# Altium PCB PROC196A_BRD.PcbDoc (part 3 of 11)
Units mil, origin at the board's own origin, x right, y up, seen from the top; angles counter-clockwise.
Board outline 3346.45 x 4921.26 mil, 8 copper layers (Top Layer, GND1, SIG1, PWR1, PWR2, SIG2, GND2, Bottom Layer), stack 54.534 mil thick; 736 components, 498 nets, 3030 pads, 1279 vias.
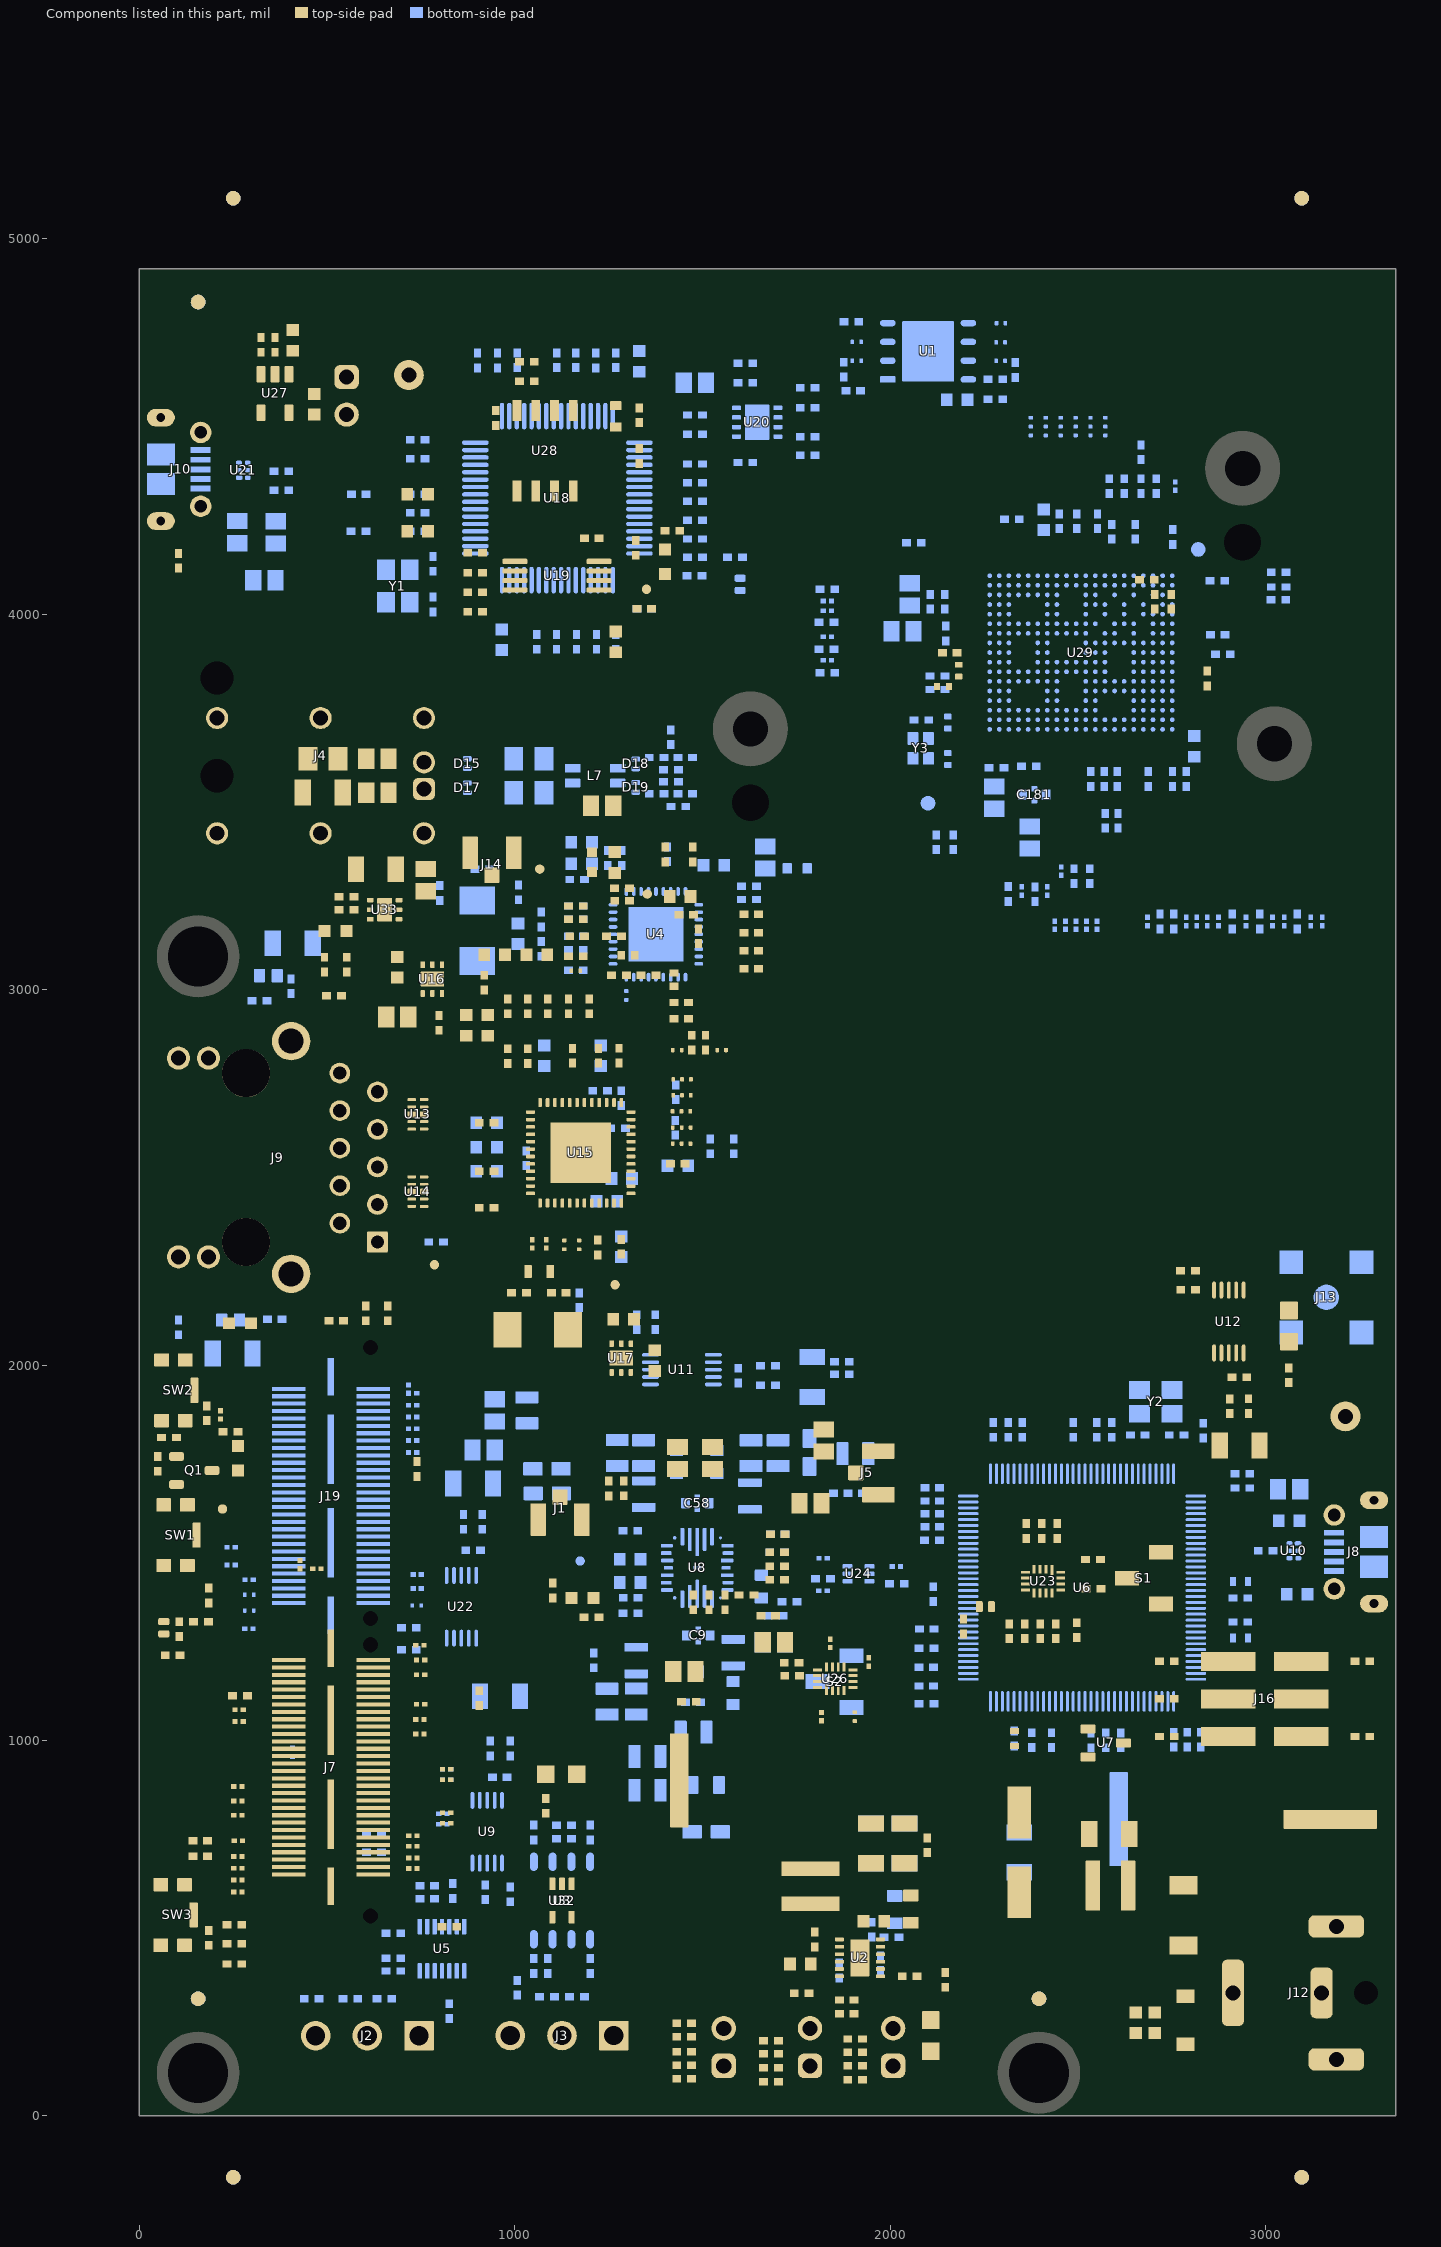
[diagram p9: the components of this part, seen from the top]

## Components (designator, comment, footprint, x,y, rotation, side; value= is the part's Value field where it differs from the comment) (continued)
U1 "GD25B64CWAG" FP-GD25B64CWAG_WSON8-IPC_C 2101.26,4700.85 r0 bottom
U2 "LM63635DQDRRRQ1" DRR0012E-MFG 1919.6,420.63 r0 top
U3 "TCAN1042HGVDQ1" D0008A_L 1125.93,573.58 r270 bottom
U4 "DP83TG720SWRNDRQ1" RND0036A 1376.2,3147.56 r0 bottom locked
U5 "TCAN1043ADYYRQ1" DYY0014A-MFG 806.31,444.86 r270 bottom
U6 "TM4C1294NCPDTT3" PDT0128A 2511.49,1407.16 r90 bottom locked
U7 "LM4040C25QDBZR" DBZ0003A_N 2574.48,993.51 r0 top
U8 "LP877451A1RXVRQ1" RXV0028A-MFG 1486.13,1459.75 r180 bottom locked
U9 "INA226AIDGSR" DGS0010A_L 926.74,756.92 r90 bottom
U10 "TPD4E004DRYR" DRY0006A 3075.82,1505.18 r180 bottom
U11 "INA226AIDGSR" DGS0010A_L 1445.36,1987.85 r0 bottom
U12 "INA226AIDGSR" DGS0010A_L 2902.35,2116.06 r270 top
U13 "TPD4E05U06DQAR" DQA0010A 742.07,2668.11 r0 top
U14 "TPD4E05U06DQAR" DQA0010A 742.07,2462.03 r0 top
U15 "DP83867ERGZR" RGZ0048B 1175.93,2565.54 r0 top
U16 "TPS73501DRVR" DRV0006A 780.58,3028.35 r90 top
U17 "TLV73310PQDRVRQ1" DRV0006A 1283.94,2018.66 r270 top
U18 "FT4232HL" LQFP64_N 1113.67,4309.69 r0 bottom
U19 "93LC46B-I/ST" TSSOP-8 1112.63,4102.86 r0 top
U20 "TPS79601DRBR" DRB0008B 1645.89,4511.81 r0 bottom
U21 "TPD4E004DRYR" DRY0006A 276.82,4383.75 r0 bottom
U22 "INA226AIDGSR" DGS0010A_L 857.87,1356.04 r90 bottom
U23 "TS3A5018RSVR" RSV0016A 2407.55,1424.47 r270 top
U24 "TMP112AIDRLR" DRL0006A 1915.92,1443.85 r180 bottom
U26 "TS3A5018RSVR" RSV0016A 1854.01,1164.54 r90 top
U27 "TPS78417QDBVRQ1" DBV0005A-MFG 361.36,4588.4 r270 top
U28 "CAV24C02WE-GT3" SOIC-8 1080.83,4435.85 r90 top
U29 "AWR2E44P" AMX0278A-MFG 2508.41,3898.25 r0 bottom
U32 "SN74LVC1G04QDCKRQ1" DCK0005A_N 1125.93,573.58 r270 top
U33 "TPS7B8133QDRVRQ1" DRV0006A 653.41,3213.22 r0 top
Y1 "NX3225SA-12.000M-STD-CRS-2" NDK_NX3225SA 688.79,4075.43 r0 bottom
Y2 "NX3225SA-16.000M-STD-CRS-2" NDK_NX3225SA 2707.65,1902.17 r270 bottom
Y3 "NX2016SA-50M-STD-CZS-3" FP-NX2016SA-50M-STD-CZS-3_SMT4_2MM0_1MM6-MFG 2081.21,3642.74 r270 bottom
Y4 "ABM3-25.000MHZ-D2Y-T" XTAL_ABM3 1061.17,2093.9 r0 top
Y5 "ABM3-25.000MHZ-D2W-T" XTAL_ABM3 899.95,3156.78 r90 bottom
ZZ1 "This Assembly Note is for PCB labels only" AssemblyNoteLabel 187.12,5373.65 r0 top
ZZ2 "These assemblies are ESD sensitive, ESD precautions shall be observed." AssemblyNote 187.12,5264.77 r0 top
ZZ3 "These assemblies must be clean and free from flux and all contaminants. Use of no clean flux is not acceptable." AssemblyNote 179,5572 r0 top
ZZ4 "These assemblies must comply with workmanship standards IPC-A-610 Class 2, unless otherwise specified." AssemblyNote 177,5497 r0 top

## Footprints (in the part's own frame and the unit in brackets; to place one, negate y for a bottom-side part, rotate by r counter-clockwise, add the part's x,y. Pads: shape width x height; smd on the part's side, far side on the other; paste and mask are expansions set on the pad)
142-0711-201 [mil] "Emerson Connectivity recommended land pattern"
  round 68 smd: 1(0,0)
  rect 63x63 smd: 2(-93.5,-93.5) 2(-93.5,93.5) 2(93.5,-93.5) 2(93.5,93.5)
  Top Layer region: -47.5,64.83 -57.02,57.02 -67.05,44.8 -74.5,30.86 -79.09,15.73 -80.64,0 -79.09,-15.73 -74.5,-30.86 -67.05,-44.8 -57.02,-57.02 -47.5,-64.83 -47.5,-140 -140.5,-140 -140.5,140 -47.5,140
  Top Layer region: 140.5,-140 47.5,-140 47.5,-64.83 57.02,-57.02 67.05,-44.8 74.5,-30.86 79.09,-15.73 80.64,0 79.09,15.73 74.5,30.86 67.05,44.8 57.02,57.02 47.5,64.83 47.5,140 140.5,140
  body extent -125,-125 125,125, height 349
0201_033L [mm] "0201"
  rect 0.36x0.32 smd mask+0.048: 1(-0.28,0) 2(0.28,0)
  body extent -0.31,-0.16 0.31,0.16, height 0.33
0201L [mm] "Data from Kemet datasheet CC101_COM dated 7/28/11"
  rect 0.36x0.32 smd mask+0.048: 1(-0.28,0) 2(0.28,0)
  body extent -0.31,-0.16 0.31,0.16, height 0.26
0402_065L [mm] "0402"
  rect 0.6x0.5 smd: 1(-0.5,0) 2(0.5,0)
  body extent -0.55,-0.3 0.55,0.3, height 0.65
0402_070 [mil] "SMD, 2-Leads, Body 1.2x0.7mm, Height 0.7mm"
  rect 15x24 smd: 1(-20,0) 2(20,0)
  body extent -24,-14 24,14, height 28
0402L [mm] "0402 from SM-752 data"
  rect 0.6x0.5 smd: 1(-0.5,0) 2(0.5,0)
  body extent -0.55,-0.3 0.55,0.3, height 0.6
0603L [mm] "0603 from SM-752 data"
  rect 0.8x0.85 smd: 1(-0.7,0) 2(0.7,0)
  silkscreen extent -0.07,-0.33 0.07,0.33, body extent -0.87,-0.47 0.87,0.47, height 1
0805_155 [mm] "SMD, 2-Leads, Body 2x1.25mm"
  rrect12% 0.825x1.55 smd: 1(-0.875,0) 2(0.875,0)
  silkscreen extent -0.15,-0.77 0.15,0.77, body extent -1.15,-0.77 1.15,0.77, height 1.55
0805_HV [mil] "0805 with 30mil clearance between pads"
  rect 50x63 smd: 1(-40,0) 2(40,0)
  silkscreen extent -74,-40 74,40, body extent -43,-29 43,29, height 57
0805L [mm] "0805 from SM-752 data"
  rect 1.1x1.4 smd: 1(-0.75,0) 2(0.75,0)
  body extent -1.1,-0.72 1.1,0.72, height 1.45
1206_180L [mm] "1206_180"
  rect 1.1x1.75 smd: 1(-1.35,0) 2(1.35,0)
  silkscreen extent -0.4,-0.77 0.4,0.77, body extent -1.75,-0.95 1.75,0.95, height 1.8
1206L [mm] "1206 from SM-752 data"
  rect 1.1x1.75 smd: 1(-1.35,0) 2(1.35,0)
  silkscreen extent -0.4,-0.77 0.4,0.77, body extent -1.7,-0.9 1.7,0.9, height 1.35
-UKCA_Filled [mil]
  silkscreen extent -118,-118 118,118
AMX0278A-MFG [mm]
  round 0.32 smd paste+0 mask+0.07: A1(-6.175,5.2) A2(-5.525,5.2) A3(-4.875,5.2) A4(-4.225,5.2) A5(-3.575,5.2) A6(-2.925,5.2) A7(-2.275,5.2) A8(-1.625,5.2) A9(-0.975,5.2) A10(-0.325,5.2) A11(0.325,5.2) A12(0.975,5.2) A13(1.625,5.2) A14(2.275,5.2) A15(2.925,5.2) A16(3.575,5.2) A17(4.225,5.2) A18(4.875,5.2) A19(5.525,5.2) A20(6.175,5.2) B1(-6.175,4.55) B2(-5.525,4.55) B3(-4.875,4.55) B4(-4.225,4.55) B5(-3.575,4.55) B6(-2.925,4.55) B7(-2.275,4.55) B8(-1.625,4.55) B9(-0.975,4.55) B10(-0.325,4.55) B11(0.325,4.55) B12(0.975,4.55) B13(1.625,4.55) B14(2.275,4.55) B15(2.925,4.55) B16(3.575,4.55) B17(4.225,4.55) B18(4.875,4.55) B19(5.525,4.55) B20(6.175,4.55) C1(-6.175,3.9) C2(-5.525,3.9) C3(-4.875,3.9) C4(-4.225,3.9) C5(-3.575,3.9) C6(-2.925,3.9) C7(-2.275,3.9) C8(-1.625,3.9) C9(-0.975,3.9) C10(-0.325,3.9) C11(0.325,3.9) C12(0.975,3.9) C16(3.575,3.9) C17(4.225,3.9) C18(4.875,3.9) C19(5.525,3.9) C20(6.175,3.9) D1(-6.175,3.25) D2(-5.525,3.25) D3(-4.875,3.25) D7(-2.275,3.25) D8(-1.625,3.25) D11(0.325,3.25) D12(0.975,3.25) D16(3.575,3.25) D17(4.225,3.25) D18(4.875,3.25) D19(5.525,3.25) D20(6.175,3.25) E1(-6.175,2.6) E2(-5.525,2.6) E3(-4.875,2.6) E7(-2.275,2.6) E8(-1.625,2.6) E11(0.325,2.6) E12(0.975,2.6) E13(1.625,2.6) E14(2.275,2.6) E15(2.925,2.6) E16(3.575,2.6) E17(4.225,2.6) E18(4.875,2.6) E19(5.525,2.6) E20(6.175,2.6) F1(-6.175,1.95) F2(-5.525,1.95) F3(-4.875,1.95) F4(-4.225,1.95) F5(-3.575,1.95) F6(-2.925,1.95) F7(-2.275,1.95) F8(-1.625,1.95) F11(0.325,1.95) F12(0.975,1.95) F13(1.625,1.95) F14(2.275,1.95) F15(2.925,1.95) F16(3.575,1.95) F17(4.225,1.95) F18(4.875,1.95) F19(5.525,1.95) F20(6.175,1.95) G1(-6.175,1.3) G2(-5.525,1.3) G3(-4.875,1.3) G4(-4.225,1.3) G5(-3.575,1.3) G6(-2.925,1.3) G7(-2.275,1.3) G8(-1.625,1.3) G9(-0.975,1.3) G10(-0.325,1.3) G11(0.325,1.3) G12(0.975,1.3) G13(1.625,1.3) G16(3.575,1.3) G17(4.225,1.3) G18(4.875,1.3) G19(5.525,1.3) G20(6.175,1.3) H1(-6.175,0.65) H2(-5.525,0.65) H3(-4.875,0.65) H6(-2.925,0.65) H7(-2.275,0.65) H8(-1.625,0.65) H9(-0.975,0.65) H10(-0.325,0.65) H11(0.325,0.65) H12(0.975,0.65) H13(1.625,0.65) H16(3.575,0.65) H17(4.225,0.65) H18(4.875,0.65) H19(5.525,0.65) H20(6.175,0.65) J1(-6.175,0) J2(-5.525,0) J3(-4.875,0) J6(-2.925,0) J7(-2.275,0) J11(0.325,0) J12(0.975,0) J13(1.625,0) J16(3.575,0) J17(4.225,0) J18(4.875,0) J19(5.525,0) J20(6.175,0) K1(-6.175,-0.65) K2(-5.525,-0.65) K3(-4.875,-0.65) K6(-2.925,-0.65) K7(-2.275,-0.65) K11(0.325,-0.65) K12(0.975,-0.65) K13(1.625,-0.65) K14(2.275,-0.65) K15(2.925,-0.65) K16(3.575,-0.65) K17(4.225,-0.65) K18(4.875,-0.65) K19(5.525,-0.65) K20(6.175,-0.65) L1(-6.175,-1.3) L2(-5.525,-1.3) L3(-4.875,-1.3) L4(-4.225,-1.3) L5(-3.575,-1.3) L6(-2.925,-1.3) L7(-2.275,-1.3) L8(-1.625,-1.3) L9(-0.975,-1.3) L10(-0.325,-1.3) L11(0.325,-1.3) L13(1.625,-1.3) L14(2.275,-1.3) L16(3.575,-1.3) L18(4.875,-1.3) L19(5.525,-1.3) L20(6.175,-1.3) M1(-6.175,-1.95) M2(-5.525,-1.95) M3(-4.875,-1.95) M4(-4.225,-1.95) M5(-3.575,-1.95) M6(-2.925,-1.95) M7(-2.275,-1.95) M8(-1.625,-1.95) M9(-0.975,-1.95) M10(-0.325,-1.95) M11(0.325,-1.95) M12(0.975,-1.95) M14(2.275,-1.95) M15(2.925,-1.95) M16(3.575,-1.95) M18(4.875,-1.95) M19(5.525,-1.95) M20(6.175,-1.95) N1(-6.175,-2.6) N2(-5.525,-2.6) N3(-4.875,-2.6) N7(-2.275,-2.6) N8(-1.625,-2.6) N11(0.325,-2.6) N13(1.625,-2.6) N15(2.925,-2.6) N17(4.225,-2.6) N18(4.875,-2.6) N19(5.525,-2.6) N20(6.175,-2.6) P1(-6.175,-3.25) P2(-5.525,-3.25) P3(-4.875,-3.25) P7(-2.275,-3.25) P8(-1.625,-3.25) P11(0.325,-3.25) P12(0.975,-3.25) P13(1.625,-3.25) P15(2.925,-3.25) P17(4.225,-3.25) P19(5.525,-3.25) P20(6.175,-3.25) R1(-6.175,-3.9) R2(-5.525,-3.9) R3(-4.875,-3.9) R4(-4.225,-3.9) R5(-3.575,-3.9) R6(-2.925,-3.9) R7(-2.275,-3.9) R8(-1.625,-3.9) R11(0.325,-3.9) R12(0.975,-3.9) R14(2.275,-3.9) R16(3.575,-3.9) R18(4.875,-3.9) R19(5.525,-3.9) R20(6.175,-3.9) T1(-6.175,-4.55) T2(-5.525,-4.55) T3(-4.875,-4.55) T4(-4.225,-4.55) T5(-3.575,-4.55) T6(-2.925,-4.55) T7(-2.275,-4.55) T8(-1.625,-4.55) T9(-0.975,-4.55) T10(-0.325,-4.55) T11(0.325,-4.55) T12(0.975,-4.55) T13(1.625,-4.55) T14(2.275,-4.55) T15(2.925,-4.55) T16(3.575,-4.55) T17(4.225,-4.55) T18(4.875,-4.55) T19(5.525,-4.55) T20(6.175,-4.55) U1(-6.175,-5.2) U2(-5.525,-5.2) U3(-4.875,-5.2) U4(-4.225,-5.2) U5(-3.575,-5.2) U6(-2.925,-5.2) U7(-2.275,-5.2) U8(-1.625,-5.2) U9(-0.975,-5.2) U10(-0.325,-5.2) U11(0.325,-5.2) U12(0.975,-5.2) U13(1.625,-5.2) U14(2.275,-5.2) U15(2.925,-5.2) U16(3.575,-5.2) U17(4.225,-5.2) U18(4.875,-5.2) U19(5.525,-5.2) U20(6.175,-5.2)
  silkscreen extent -6.8,-6.05 6.8,6.05, body extent -6.75,-6 6.75,6, height 1.24
AssemblyNote [mil] "Assembly Note"
AssemblyNoteLabel [mil] "Assembly Note for PCB Labels"
CE_Mark_5mm [mil] "Minimum text height for CE Mark"
  silkscreen extent -138,-98 138,98
CONN_105017-0001 [mm] "Molex Micro USB-B"
  rect 0.4x1.35 smd: 1(-1.3,1.35) 2(-0.65,1.35) 3(0,1.35) 4(0.65,1.35) 5(1.3,1.35)
  oval 1.2x1.9 hole 0.6 slot 1.3 at 90 deg: 6(-3.5,-1.35) 9(3.5,-1.35)
  rect 1.5x1.9 smd: 7(-1,-1.35) 8(1,-1.35)
  round 1.45 hole 0.85: 10(2.5,1.35) 11(-2.5,1.35)
  Top Layer region: 3.5,-2.3 2.3,-2.3 2.3,-0.4 3.5,-0.4
  Top Layer region: -3.5,-0.4 -2.3,-0.4 -2.3,-2.3 -3.5,-2.3
  silkscreen extent -4.1,-0.2 4.1,1.4, body extent -4.1,-3.93 4.1,1.5, height 2.72
CUI_PJ-063AH [mm] "DC POWER JACK, R/A, TH"
  rrect50% 1.5x4.5 hole 1 square: 1(-4.5,0)
  rrect50% 1.5x3.45 hole 1 square: 2(1.5,0)
  oval 1.35x1.3 hole 1.6 unplated mask+0.102: ALIGN(4.5,0)
  rrect50% 3.75x1.5 hole 1 square: S1(2.5,-4.5) S2(2.5,4.5)
  body extent -5.5,-5.15 7.5,5.15, height 9
D0008A_L [mm] "SOIC, 8-Leads, Body 4.9x3.9mm, Pitch 1.27mm, IPC High Density"
  oval 1.25x0.55 smd: 1(-2.625,1.905) 2(-2.625,0.635) 3(-2.625,-0.635) 4(-2.625,-1.905) 5(2.625,-1.905) 6(2.625,-0.635) 7(2.625,0.635) 8(2.625,1.905)
  silkscreen extent -3.1,-2.5 0.9,2.5, body extent -3,-2.45 3,2.45, height 1.63
DBV0005A-MFG [mm]
  rrect17% 1.1x0.6 smd paste+0 mask+0: 1(-1.3,0.95) 2(-1.3,0) 3(-1.3,-0.95) 4(1.3,-0.95) 5(1.3,0.95)
  silkscreen extent -1.5,-1.53 0.87,2.01, body extent -1.95,-1.78 1.95,1.78, height 0.25
DBZ0003A_N [mm] "SOT23, 3-Leads, Body 2.9x1.3mm, Pitch 0.95mm, Lead Span 2.4mm, IPC Medium Density"
  rrect17% 1x0.6 smd: 1(-1.2,0.95) 2(-1.2,-0.95) 3(1.2,0)
  silkscreen extent 0.2,-1.5 0.7,1.5, body extent -1.26,-1.46 1.26,1.46, height 0.98
DCK0005A_N [mm] "SOT353, 5-Leads, Body 2x1.3mm, Pitch 0.65mm, Lead Span 2.1mm, IPC Medium Density"
  rrect25% 0.85x0.4 smd: 1(-1.125,0.65) 2(-1.125,0) 3(-1.125,-0.65) 4(1.125,-0.65) 5(1.125,0.65)
  silkscreen extent -1.48,-1.02 0.55,1.1, body extent -1.14,-1 1.14,1, height 0.95
DGS0010A_L [mm] "TSSOP, 10-Leads, Body 3x3mm, Pitch 0.5mm, IPC High Density"
  oval 1.15x0.25 smd: 1(-2.125,1) 2(-2.125,0.5) 3(-2.125,0) 4(-2.125,-0.5) 5(-2.125,-1) 6(2.125,-1) 7(2.125,-0.5) 8(2.125,0) 9(2.125,0.5) 10(2.125,1)
  silkscreen extent -2.65,-1.55 0.9,1.55, body extent -2.45,-1.5 2.45,1.5, height 0.96
DPY0002A [mm] "X1SON-2"
  rrect57% 0.35x0.6 smd paste-0.5 mask-0.05: 1(-0.325,0) 2(0.325,0)
  rrect33% 0.3x0.5 on Bottom Paste: 1S(-0.35,0) 2S(0.35,0)
  silkscreen extent -0.85,-0.02 -0.8,0.03, body extent -0.5,-0.3 0.5,0.3, height 0.45
DQA0010A [mm] "SON, 10-Leads, Body 1x2.5mm, Pitch 0.5mm, TI Recommended"
  rrect50% 0.565x0.2 smd: 1(-0.417,1) 2(-0.417,0.5) 4(-0.417,-0.5) 5(-0.417,-1) 6(0.417,-1) 7(0.417,-0.5) 9(0.417,0.5) 10(0.417,1)
  rrect28% 0.565x0.36 on Top Paste: 3(-0.417,0) 8(0.417,0)
  rrect25% 0.565x0.4 smd paste-0.2: 3(-0.417,0) 8(0.417,0)
  silkscreen extent -0.67,-1.45 0.55,1.45, body extent -0.55,-1.3 0.55,1.3, height 0.56
DRB0008B [mm] "SON, 8-Leads, Body 3x3mm, Pitch 0.65mm, Thermal Pad 2.4x1.65mm, TI Recommended"
  rrect33% 0.6x0.3 smd: 1(-1.4,0.975) 2(-1.4,0.325) 3(-1.4,-0.325) 4(-1.4,-0.975) 5(1.4,-0.975) 6(1.4,-0.325) 7(1.4,0.325) 8(1.4,0.975)
  rrect9% 1.47x1.06 on Bottom Paste: 9(0,-0.63) 9(0,0.63)
  rrect6% 1.65x2.4 smd paste-1.2: 9(0,0)
  silkscreen extent -1.73,-1.73 1.73,1.73, body extent -1.5,-1.5 1.5,1.5, height 0.96
DRL0006A [mm] "SOTFL, 6-Flat Leads, Body 1.2x1.6x0.6mm, Pitch 0.5mm, TI recommended"
  rrect33% 0.67x0.3 smd: 1(-0.74,0.5) 2(-0.74,0) 3(-0.74,-0.5) 4(0.74,-0.5) 5(0.74,0) 6(0.74,0.5)
  silkscreen extent -0.9,-0.95 0.5,0.95, body extent -0.8,-0.8 0.8,0.8, height 0.61
DRR0012E-MFG [mm]
  rrect40% 0.62x0.25 smd paste+0 mask+0: 1(-1.39,1.25) 2(-1.39,0.75) 3(-1.39,0.25) 4(-1.39,-0.25) 5(-1.39,-0.75) 6(-1.39,-1.25) 7(1.39,-1.25) 8(1.39,-0.75) 9(1.39,-0.25) 10(1.39,0.25) 11(1.39,0.75) 12(1.39,1.25)
  rrect8% 1.3x2.5 smd paste-1000 mask+0: 13(0,0)
  silkscreen extent -2.37,-1.75 1.55,1.75, body extent -1.8,-1.65 1.8,1.65, height 0.25
DRV0006A [mm] "SON, 6-Leads, Body 2x2mm, Pitch 0.65mm, Thermal Pad 1.6x1mm, TI Recommended"
  rrect33% 0.45x0.3 smd: 1(-0.975,0.65) 2(-0.975,0) 3(-0.975,-0.65) 4(0.975,-0.65) 5(0.975,0) 6(0.975,0.65)
  rrect14% 1x0.7 on Top Paste: 7(0,0.45) 7(0,-0.45)
  rrect10% 1x1.6 smd paste-0.5: 7(0,0)
  silkscreen extent -1.05,-1.2 1.05,1.2, body extent -1.05,-1.05 1.05,1.05, height 0.81
DRY0006A [mm] "USON-6"
  rrect67% 0.45x0.3 smd paste-0.05 mask-0.05: 1(-0.275,0.5)
  rrect67% 0.4x0.3 smd paste-0.05 mask-0.05: 2(-0.3,0) 3(-0.3,-0.5) 4(0.3,-0.5) 5(0.3,0) 6(0.3,0.5)
  body extent -0.5,-0.72 0.5,0.73, height 0.58
DYY0014A-MFG [mm]
  rrect33% 1.05x0.3 smd paste+0 mask+0: 1(-1.5,1.5) 2(-1.5,1) 3(-1.5,0.5) 4(-1.5,0) 5(-1.5,-0.5) 6(-1.5,-1) 7(-1.5,-1.5) 8(1.5,-1.5) 9(1.5,-1) 10(1.5,-0.5) 11(1.5,0) 12(1.5,0.5) 13(1.5,1) 14(1.5,1.5)
  silkscreen extent -2.72,-2.15 1.05,2.15, body extent -1.63,-2.1 1.63,2.1, height 1.1
ESD_Overlay_Small [mil]
  silkscreen extent -62,-48 64,61
FCC_disclaimer [mil]
Fiducial10-20 [mm]
  round 1 smd paste-1 mask+0.5: 1(0,0)
  Top Layer keep-out circle w1.178: c0,0 r0.5
"FP-1909763-1_SMT_JACK _CONN-MFG" [mm]
  rrect10% 1x1.05 smd paste+0 mask+0: 1(0,-1.6)
  rrect10% 1.05x2.2 smd paste+0 mask+0: 2(-1.475,-0.075) 3(1.475,-0.075)
  silkscreen extent -1.43,-2.8 1.43,1.5, body extent -2.1,-2.22 2.1,1.6, height 0.25
FP-ACT1210L-201-2P-TL00_SMD4-MFG [mm]
  rrect17% 1.05x0.6 smd paste+0 mask+0: 1(-1.525,0.5) 2(-1.525,-0.5) 3(1.525,-0.5) 4(1.525,0.5)
  silkscreen extent -1.83,-1.35 1.7,1.87, body extent -1.95,-1.25 1.95,1.25, height 2.5
FP-BLM18AG102SH1D_0603-MFG [mm]
  rrect15% 0.65x0.7 smd paste+0 mask+0: 1(-0.675,0) 2(0.675,0)
  silkscreen extent -0.87,-0.72 0.87,0.72, body extent -0.8,-0.4 0.8,0.4, height 0.95
"FP-BLM18KG601SH1_0603 (1608 Metric)-MFG" [mm]
  rrect15% 0.65x0.7 smd paste+0 mask+0: 1(-0.675,0) 2(0.675,0)
  silkscreen extent -0.87,-0.75 0.87,0.75, body extent -1.1,-0.58 1.1,0.58, height 0.25
FP-C0603C104K4RACAUTO_0603-MFG [mm]
  rrect13% 0.75x0.9 smd paste+0 mask+0: 1(-0.6,0) 2(0.6,0)
  silkscreen extent -0.87,-0.85 0.88,0.85, body extent -0.8,-0.4 0.8,0.4, height 0.87
FP-CGA4J1X7R1H475K125AC_0805-MFG [mm]
  rrect13% 0.8x1.05 smd paste+0 mask+0: 1(-0.925,0) 2(0.925,0)
  silkscreen extent -0.15,-0.72 0.15,0.72, body extent -1.43,-0.82 1.43,0.82, height 0.25
FP-CRCW06031M00FKEAC_0603-MFG [mm]
  rrect20% 0.5x0.9 smd paste+0 mask+0: 1(-0.75,0) 2(0.75,0)
  silkscreen extent -0.82,-0.85 0.82,0.85, body extent -1.1,-0.55 1.1,0.55, height 0.25
FP-ERJ-1GNF33R2C_0201-MFG [mm]
  rrect40% 0.25x0.3 smd paste+0 mask+0: 1(-0.3,0) 2(0.3,0)
  silkscreen extent -0.32,-0.54 0.32,0.54, body extent -0.3,-0.15 0.3,0.15, height 0.26
FP-GCJ188C70J475KE02J_0603-MFG [mm]
  rrect13% 0.75x0.9 smd paste+0 mask+0: 1(-0.775,0) 2(0.775,0)
  silkscreen extent -0.9,-0.87 0.9,0.87, body extent -0.8,-0.4 0.8,0.4, height 1
FP-GCM1555C1H3R9BA16D_0402-MFG [mm]
  rrect25% 0.4x0.5 smd paste+0 mask+0: 1(-0.4,0) 2(0.4,0)
  silkscreen extent -0.53,-0.65 0.53,0.65, body extent -0.5,-0.25 0.5,0.25, height 0.55
FP-GD25B64CWAG_WSON8-IPC_C [mm]
  rrect23% 1.059x0.436 smd paste+0 mask+0: 1(-2.727,1.905)
  rrect100% 1.059x0.436 smd paste+0 mask+0: 2(-2.727,0.635) 3(-2.727,-0.635) 4(-2.727,-1.905) 5(2.727,-1.905) 6(2.727,-0.635) 7(2.727,0.635) 8(2.727,1.905)
  rrect3% 3.5x4.1 smd paste-1000 mask+0: 9(0,0)
  silkscreen extent -3.92,-2.5 3,2.5, body extent -3,-2.5 3,2.5, height 0.8
FP-GRT155R70J105KE01D_0402-MFG [mm]
  rrect25% 0.4x0.5 smd paste+0 mask+0: 1(-0.4,0) 2(0.4,0)
  silkscreen extent -0.53,-0.63 0.53,0.63, body extent -0.5,-0.25 0.5,0.25, height 0.55
FP-HCJ0603ZT0R00_0603-MFG [mm]
  rrect11% 1.3x0.92 smd paste+0 mask+0: 1(-0.95,0) 2(0.95,0)
  silkscreen extent -0.9,-0.83 0.9,0.83, body extent -0.8,-0.4 0.8,0.4, height 0.7
FP-LPJG16414A4NL_CONN_RJ45-MFG [mm]
  rrect7% 1.4x1.4 hole 0.9 paste-2539.97 mask+0: 1(-5.715,9.015)
  round 1.4 hole 0.9 paste-2539.97 mask+0: 2(-4.445,6.475) 3(-3.175,9.015) 4(-1.905,6.475) 5(-0.635,9.015) 6(0.635,6.475) 7(1.905,9.015) 8(3.175,6.475) 9(4.445,9.015) 10(5.715,6.475)
  round 1.57 hole 1.02 paste-2539.97 mask+0: 11(6.725,-2.415) 12(6.725,-4.445) 13(-6.725,-2.415) 14(-6.725,-4.445)
  round 2.6 hole 1.7 paste-2539.97 mask+0: 15(-7.875,3.175) 16(7.875,3.175)
  round 3.25 hole 3.25 unplated paste-2539.97 mask+0: ""(-5.715,0.125) ""(5.715,0.125)
  silkscreen extent -9.72,-10.75 8.1,10.75, body extent -9.94,-10.88 9.87,10.63, height 15.47
FP-MPZ2012S101ATD25_0805-MFG [mm]
  rrect13% 0.8x1.2 smd paste+0 mask+0: 1(-0.9,0) 2(0.9,0)
  silkscreen extent -0.13,-0.72 0.13,0.72, body extent -1,-0.63 1,0.63, height 1.05
FP-NFM18HC105C1C3D_0603-MFG [mm]
  rrect17% 0.6x0.7 smd paste+0 mask+0: 1(-0.8,0) 3(0.8,0)
  rrect25% 0.4x0.4 smd paste+0 mask+0: 2(0,-0.4) 2(0,0.4)
  silkscreen extent -1.66,-0.97 0.85,0.97, body extent -0.8,-0.4 0.8,0.4, height 0.7
FP-NX2016SA-50M-STD-CZS-3_SMT4_2MM0_1MM6-MFG [mm]
  rrect13% 0.85x0.75 smd paste+0 mask+0: 1(-0.675,-0.525) 2(0.675,-0.525) 3(0.675,0.525) 4(-0.675,0.525)
  silkscreen extent -1.48,-1.58 1.48,0.85, body extent -1,-0.8 1,0.8, height 0.5
FP-OSTTF030161_PTH_TERMINAL_BLOCK-MFG [mm]
  rrect5% 2x2 hole 1.3 paste-2539.97 mask+0: 1(-3.5,-0.45)
  round 2 hole 1.3 paste-2539.97 mask+0: 2(0,-0.45) 3(3.5,-0.45)
  silkscreen extent -6.63,-4.3 5.9,4.3, body extent -6,-4.4 6,4.4, height 0.25
"FP-TFM201610ALMAR24MTAA_0806 (2016 Metric)-MFG" [mm]
  rrect17% 0.6x1.6 smd paste+0 mask+0: 1(-0.9,0) 2(0.9,0)
  silkscreen extent -0.23,-0.9 0.23,0.9, body extent -1,-0.8 1,0.8, height 1
FP-XAL4030-472MEC_SMD2-MFG [mm]
  rrect10% 0.98x3.4 smd paste+0 mask+0: 1(-1.185,0) 2(1.185,0)
  silkscreen extent -2.15,-2.15 2.15,2.15, body extent -2,-2 2,2, height 3.1
IEC_HotSurface_Small [mil]
  silkscreen extent -107,-93 107,92
Johnson_128-0711-201 [mm] "UMC Straight Jack Receptacle, 50 Ohm, SMT"
  rrect10% 1x1.05 smd: 1(0,1.525)
  rrect10% 1.05x2.2 smd: 2(-1.475,0) 3(1.475,0)
  silkscreen extent -0.6,-1.3 0.6,-1.3, body extent -1.5,-1.55 1.5,1.55, height 1.25
Keystone5001 [mil] "For Keystone 500x miniature loop terminals"
  round 80 hole 40: 1(0,0)
  silkscreen extent -52,-52 52,52, body extent -49,-49 49,49, height 182
Label_650x200 [mil] "Thermal Transfer Label"
  round 1 on Mech14: 0(0,0)
  silkscreen extent -325,-100 325,100, body extent -325,-100 325,100, height 1
LED_SMLP12_ORANGE [mm] "Rohm Semiconductor"
  rect 0.5x0.6 smd mask+0.08: 1(-0.45,0) 2(0.45,0)
  silkscreen extent 0.92,0.21 0.92,0.3, body extent -0.55,-0.35 0.55,0.35, height 0.25
LED_SMLP12_YELLOW [mm] "Rohm Semiconductor"
  rect 0.5x0.6 smd mask+0.08: 1(-0.45,0) 2(0.45,0)
  silkscreen extent 0.92,-0.3 0.92,0.3, body extent -0.55,-0.35 0.55,0.35, height 0.25
LQFP64_N [mm] "Thin QFP, 64-Leads, Body 10x10mm, Pitch 0.5mm, IPC Medium Density"
  oval 1.8x0.3 smd: 1(-5.55,3.75) 2(-5.55,3.25) 3(-5.55,2.75) 4(-5.55,2.25) 5(-5.55,1.75) 6(-5.55,1.25) 7(-5.55,0.75) 8(-5.55,0.25) 9(-5.55,-0.25) 10(-5.55,-0.75) 11(-5.55,-1.25) 12(-5.55,-1.75) 13(-5.55,-2.25) 14(-5.55,-2.75) 15(-5.55,-3.25) 16(-5.55,-3.75) 33(5.55,-3.75) 34(5.55,-3.25) 35(5.55,-2.75) 36(5.55,-2.25) 37(5.55,-1.75) 38(5.55,-1.25) 39(5.55,-0.75) 40(5.55,-0.25) 41(5.55,0.25) 42(5.55,0.75) 43(5.55,1.25) 44(5.55,1.75) 45(5.55,2.25) 46(5.55,2.75) 47(5.55,3.25) 48(5.55,3.75)
  oval 0.3x1.8 smd: 17(-3.75,-5.55) 18(-3.25,-5.55) 19(-2.75,-5.55) 20(-2.25,-5.55) 21(-1.75,-5.55) 22(-1.25,-5.55) 23(-0.75,-5.55) 24(-0.25,-5.55) 25(0.25,-5.55) 26(0.75,-5.55) 27(1.25,-5.55) 28(1.75,-5.55) 29(2.25,-5.55) 30(2.75,-5.55) 31(3.25,-5.55) 32(3.75,-5.55) 49(3.75,5.55) 50(3.25,5.55) 51(2.75,5.55) 52(2.25,5.55) 53(1.75,5.55) 54(1.25,5.55) 55(0.75,5.55) 56(0.25,5.55) 57(-0.25,5.55) 58(-0.75,5.55) 59(-1.25,5.55) 60(-1.75,5.55) 61(-2.25,5.55) 62(-2.75,5.55) 63(-3.25,5.55) 64(-3.75,5.55)
  silkscreen extent -5.67,-4.25 4.25,4.57, body extent -5,-5 5,5, height 1.6
"LS L29K_Red" [mm] "SMD, 2-Leads, Body 1.3x0.8mm"
  rect 0.8x0.8 smd paste-0.4: 1(-0.75,0) 2(0.75,0)
  silkscreen extent -0.1,-0.5 1.45,0.5, body extent -0.9,-0.45 0.9,0.45, height 0.67
NDK_NX3225SA [mm] "NDK"
  rect 1.2x1.4 smd: 1(-0.8,1.1) 2(-0.8,-1.1) 3(0.8,-1.1) 4(0.8,1.1)
  body extent -1.3,-1.65 1.3,1.65, height 0.7
Net-Tie_50milWide_30milLong [mil] "50mil net tie, no solder mask opening, no solder paste"
  rect 30x50 on Mid5 paste-20 mask-20: 1(-15,0) 2(15,0)
PDT0128A [mm] "Thin QFP, 128-Leads, Body 14x14mm, Pitch 0.4mm"
  oval 1.4x0.2 smd: 1(-7.7,6.2) 2(-7.7,5.8) 3(-7.7,5.4) 4(-7.7,5) 5(-7.7,4.6) 6(-7.7,4.2) 7(-7.7,3.8) 8(-7.7,3.4) 9(-7.7,3) 10(-7.7,2.6) 11(-7.7,2.2) 12(-7.7,1.8) 13(-7.7,1.4) 14(-7.7,1) 15(-7.7,0.6) 16(-7.7,0.2) 17(-7.7,-0.2) 18(-7.7,-0.6) 19(-7.7,-1) 20(-7.7,-1.4) 21(-7.7,-1.8) 22(-7.7,-2.2) 23(-7.7,-2.6) 24(-7.7,-3) 25(-7.7,-3.4) 26(-7.7,-3.8) 27(-7.7,-4.2) 28(-7.7,-4.6) 29(-7.7,-5) 30(-7.7,-5.4) 31(-7.7,-5.8) 32(-7.7,-6.2) 65(7.7,-6.2) 66(7.7,-5.8) 67(7.7,-5.4) 68(7.7,-5) 69(7.7,-4.6) 70(7.7,-4.2) 71(7.7,-3.8) 72(7.7,-3.4) 73(7.7,-3) 74(7.7,-2.6) 75(7.7,-2.2) 76(7.7,-1.8) 77(7.7,-1.4) 78(7.7,-1) 79(7.7,-0.6) 80(7.7,-0.2) 81(7.7,0.2) 82(7.7,0.6) 83(7.7,1) 84(7.7,1.4) 85(7.7,1.8) 86(7.7,2.2) 87(7.7,2.6) 88(7.7,3) 89(7.7,3.4) 90(7.7,3.8) 91(7.7,4.2) 92(7.7,4.6) 93(7.7,5) 94(7.7,5.4) 95(7.7,5.8) 96(7.7,6.2)
  oval 0.2x1.4 smd: 33(-6.2,-7.7) 34(-5.8,-7.7) 35(-5.4,-7.7) 36(-5,-7.7) 37(-4.6,-7.7) 38(-4.2,-7.7) 39(-3.8,-7.7) 40(-3.4,-7.7) 41(-3,-7.7) 42(-2.6,-7.7) 43(-2.2,-7.7) 44(-1.8,-7.7) 45(-1.4,-7.7) 46(-1,-7.7) 47(-0.6,-7.7) 48(-0.2,-7.7) 49(0.2,-7.7) 50(0.6,-7.7) 51(1,-7.7) 52(1.4,-7.7) 53(1.8,-7.7) 54(2.2,-7.7) 55(2.6,-7.7) 56(3,-7.7) 57(3.4,-7.7) 58(3.8,-7.7) 59(4.2,-7.7) 60(4.6,-7.7) 61(5,-7.7) 62(5.4,-7.7) 63(5.8,-7.7) 64(6.2,-7.7) 97(6.2,7.7) 98(5.8,7.7) 99(5.4,7.7) 100(5,7.7) 101(4.6,7.7) 102(4.2,7.7) 103(3.8,7.7) 104(3.4,7.7) 105(3,7.7) 106(2.6,7.7) 107(2.2,7.7) 108(1.8,7.7) 109(1.4,7.7) 110(1,7.7) 111(0.6,7.7) 112(0.2,7.7) 113(-0.2,7.7) 114(-0.6,7.7) 115(-1,7.7) 116(-1.4,7.7) 117(-1.8,7.7) 118(-2.2,7.7) 119(-2.6,7.7) 120(-3,7.7) 121(-3.4,7.7) 122(-3.8,7.7) 123(-4.2,7.7) 124(-4.6,7.7) 125(-5,7.7) 126(-5.4,7.7) 127(-5.8,7.7) 128(-6.2,7.7)
  silkscreen extent -7.7,-6.3 6.3,7, body extent -8,-8 8,8, height 1.07
RGZ0048B [mm] "QFN, 48-Leads, Body 7x7mm, Pitch 0.5mm, Thermal Pad 5.15x5.15mm, TI Recommended"
  rrect42% 0.6x0.24 smd: 1(-3.4,2.75) 2(-3.4,2.25) 3(-3.4,1.75) 4(-3.4,1.25) 5(-3.4,0.75) 6(-3.4,0.25) 7(-3.4,-0.25) 8(-3.4,-0.75) 9(-3.4,-1.25) 10(-3.4,-1.75) 11(-3.4,-2.25) 12(-3.4,-2.75) 25(3.4,-2.75) 26(3.4,-2.25) 27(3.4,-1.75) 28(3.4,-1.25) 29(3.4,-0.75) 30(3.4,-0.25) 31(3.4,0.25) 32(3.4,0.75) 33(3.4,1.25) 34(3.4,1.75) 35(3.4,2.25) 36(3.4,2.75)
  rrect42% 0.24x0.6 smd: 13(-2.75,-3.4) 14(-2.25,-3.4) 15(-1.75,-3.4) 16(-1.25,-3.4) 17(-0.75,-3.4) 18(-0.25,-3.4) 19(0.25,-3.4) 20(0.75,-3.4) 21(1.25,-3.4) 22(1.75,-3.4) 23(2.25,-3.4) 24(2.75,-3.4) 37(2.75,3.4) 38(2.25,3.4) 39(1.75,3.4) 40(1.25,3.4) 41(0.75,3.4) 42(0.25,3.4) 43(-0.25,3.4) 44(-0.75,3.4) 45(-1.25,3.4) 46(-1.75,3.4) 47(-2.25,3.4) 48(-2.75,3.4)
  rrect9% 1.17x1.17 on Top Paste: 49(-1.37,-1.37) 49(-1.37,0) 49(-1.37,1.37) 49(0,-1.37) 49(0,0) 49(0,1.37) 49(1.37,-1.37) 49(1.37,0) 49(1.37,1.37)
  rrect2% 4.1x4.1 smd paste-2.575: 49(0,0)
  silkscreen extent -3.72,-3.72 3.72,3.72, body extent -3.5,-3.5 3.5,3.5, height 1.01
RND0036A [mm] "TI"
  oval 0.6x0.25 smd: 1(-2.9,2) 2(-2.9,1.5) 3(-2.9,1) 4(-2.9,0.5) 5(-2.9,0) 6(-2.9,-0.5) 7(-2.9,-1) 8(-2.9,-1.5) 9(-2.9,-2) 19(2.9,-2) 20(2.9,-1.5) 21(2.9,-1) 22(2.9,-0.5) 23(2.9,0) 24(2.9,0.5) 25(2.9,1) 26(2.9,1.5) 27(2.9,2)
  oval 0.25x0.6 smd: 10(-2,-2.9) 11(-1.5,-2.9) 12(-1,-2.9) 13(-0.5,-2.9) 14(0,-2.9) 15(0.5,-2.9) 16(1,-2.9) 17(1.5,-2.9) 18(2,-2.9) 28(2,2.9) 29(1.5,2.9) 30(1,2.9) 31(0.5,2.9) 32(0,2.9) 33(-0.5,2.9) 34(-1,2.9) 35(-1.5,2.9) 36(-2,2.9)
  rect 3.7x3.7 smd paste-1.85: 37(0,0)
  silkscreen extent -3.17,-3.17 3.17,3.2, body extent -3,-3 3,3, height 0.81
RSV0016A [mm] "QFN, 16-Leads, Body 1.8x2.6mm, Pitch 0.4mm, TI Recommended"
  rect 0.7x0.2 smd: 1(-0.75,0.6)
  rect 0.6x0.2 smd: 2(-0.8,0.2) 3(-0.8,-0.2) 4(-0.8,-0.6) 9(0.8,-0.6) 10(0.8,-0.2) 11(0.8,0.2) 12(0.8,0.6)
  rect 0.2x0.6 smd: 5(-0.6,-1.2) 6(-0.2,-1.2) 7(0.2,-1.2) 8(0.6,-1.2) 13(0.6,1.2) 14(0.2,1.2) 15(-0.2,1.2) 16(-0.6,1.2)
  silkscreen extent -1.08,-1.33 1.08,1.45, body extent -0.92,-1.32 0.92,1.33, height 0.56
RXV0028A-MFG [mm]
  round 0.195 smd paste+0 mask+0: 1(-1.573,2.03) 9(-1.573,-2.03)
  rrect40% 0.8x0.25 smd paste+0 mask+0: 2(-2.05,1.5) 8(-2.05,-1.5) 16(2.05,-1.5) 22(2.05,1.5)
  rrect40% 0.725x0.25 smd paste+0 mask+0: 3(-2.087,1) 7(-2.087,-1) 17(2.087,-1) 21(2.087,1)
  rrect40% 0.85x0.25 smd paste+0 mask+0: 4(-2.025,0.5) 6(-2.025,-0.5) 18(2.025,-0.5) 20(2.025,0.5)
  rrect40% 0.6x0.25 smd paste+0 mask+0: 5(-1.95,0) 5-19(0,0) 19(1.95,0)
  rrect40% 0.25x1.175 smd paste+0 mask+0: 10(-1,-2.113) 14(1,-2.113) 24(1,2.113) 28(-1,2.113)
  rrect40% 0.25x1.55 smd paste-1000 mask+0: 11(-0.5,-1.925) 13(0.5,-1.925) 25(0.5,1.925) 27(-0.5,1.925)
  rrect40% 0.25x1.9 smd paste-1000 mask+0: 12(0,-1.75) 26(0,1.75)
  round 0.243 smd paste+0 mask+0: 15(1.53,-2.03) 23(1.53,2.03)
  Top Layer region: -2.45,2.075 -2.443,2.1 -2.425,2.118 -2.4,2.125 -2.4,2.125 -1.625,2.125 -1.625,2.65 -1.618,2.675 -1.6,2.693 -1.575,2.7 -1.575,2.7 -1.425,2.7 -1.406,2.696 -1.39,2.685 -1.379,2.669 -1.375,2.65 -1.375,2.65 -1.375,1.925 -1.379,1.906 -1.39,1.89 -1.406,1.879 -1.425,1.875 -1.425,1.875 -2.4,1.875 -2.419,1.879 -2.435,1.89 -2.446,1.906 -2.45,1.925 -2.45,1.925
  Top Layer region: -2.45,-2.075 -2.443,-2.1 -2.425,-2.118 -2.4,-2.125 -2.4,-2.125 -1.625,-2.125 -1.625,-2.65 -1.618,-2.675 -1.6,-2.693 -1.575,-2.7 -1.575,-2.7 -1.425,-2.7 -1.406,-2.696 -1.39,-2.685 -1.379,-2.669 -1.375,-2.65 -1.375,-2.65 -1.375,-1.925 -1.379,-1.906 -1.39,-1.89 -1.406,-1.879 -1.425,-1.875 -1.425,-1.875 -2.4,-1.875 -2.419,-1.879 -2.435,-1.89 -2.446,-1.906 -2.45,-1.925 -2.45,-1.925
  Top Layer region: 2.45,-2.075 2.443,-2.1 2.425,-2.118 2.4,-2.125 2.4,-2.125 1.625,-2.125 1.625,-2.65 1.618,-2.675 1.6,-2.693 1.575,-2.7 1.575,-2.7 1.425,-2.7 1.4,-2.693 1.382,-2.675 1.375,-2.65 1.375,-2.65 1.375,-1.925 1.379,-1.906 1.39,-1.89 1.406,-1.879 1.425,-1.875 1.425,-1.875 2.4,-1.875 2.419,-1.879 2.435,-1.89 2.446,-1.906 2.45,-1.925 2.45,-1.925
  Top Layer region: 2.45,2.075 2.443,2.1 2.425,2.118 2.4,2.125 2.4,2.125 1.625,2.125 1.625,2.65 1.618,2.675 1.6,2.693 1.575,2.7 1.575,2.7 1.425,2.7 1.4,2.693 1.382,2.675 1.375,2.65 1.375,2.65 1.375,1.925 1.379,1.906 1.39,1.89 1.406,1.879 1.425,1.875 1.425,1.875 2.4,1.875 2.419,1.879 2.435,1.89 2.446,1.906 2.45,1.925 2.45,1.925
  Top Layer region: -2.45,0.075 -2.443,0.1 -2.425,0.118 -2.4,0.125 -2.4,0.125 -0.625,0.125 -0.625,0.4 0.625,0.4 0.625,0.125 2.4,0.125 2.425,0.118 2.443,0.1 2.45,0.075 2.45,0.075 2.45,-0.075 2.443,-0.1 2.425,-0.118 2.4,-0.125 2.4,-0.125 0.625,-0.125 0.625,-0.4 -0.625,-0.4 -0.625,-0.125 -2.4,-0.125 -2.425,-0.118 -2.443,-0.1 -2.45,-0.075 -2.45,-0.075
  silkscreen extent -3.13,-3.1 2.3,3.1, body extent -2.25,-2.5 2.25,2.5, height 1
Samtec_QSH-030-01-X-D-A [mm] "Receptacle, 0.5 mm, 30x2, TH"
  rect 2.27x0.279 smd: 1(-2.865,7.25) 2(2.865,7.25) 3(-2.865,6.75) 4(2.865,6.75) 5(-2.865,6.25) 6(2.865,6.25) 7(-2.865,5.75) 8(2.865,5.75) 9(-2.865,5.25) 10(2.865,5.25) 11(-2.865,4.75) 12(2.865,4.75) 13(-2.865,4.25) 14(2.865,4.25) 15(-2.865,3.75) 16(2.865,3.75) 17(-2.865,3.25) 18(2.865,3.25) 19(-2.865,2.75) 20(2.865,2.75) 21(-2.865,2.25) 22(2.865,2.25) 23(-2.865,1.75) 24(2.865,1.75) 25(-2.865,1.25) 26(2.865,1.25) 27(-2.865,0.75) 28(2.865,0.75) 29(-2.865,0.25) 30(2.865,0.25) 31(-2.865,-0.25) 32(2.865,-0.25) 33(-2.865,-0.75) 34(2.865,-0.75) 35(-2.865,-1.25) 36(2.865,-1.25) 37(-2.865,-1.75) 38(2.865,-1.75) 39(-2.865,-2.25) 40(2.865,-2.25) 41(-2.865,-2.75) 42(2.865,-2.75) 43(-2.865,-3.25) 44(2.865,-3.25) 45(-2.865,-3.75) 46(2.865,-3.75) 47(-2.865,-4.25) 48(2.865,-4.25) 49(-2.865,-4.75) 50(2.865,-4.75) 51(-2.865,-5.25) 52(2.865,-5.25) 53(-2.865,-5.75) 54(2.865,-5.75) 55(-2.865,-6.25) 56(2.865,-6.25) 57(-2.865,-6.75) 58(2.865,-6.75) 59(-2.865,-7.25) 60(2.865,-7.25)
  round 0 hole 1.02 unplated: MH1(2.67,10.065) MH2(2.67,-10.065)
  rect 0.43x2.54 smd: MP1(0,8.065) MP4(0,-8.065)
  rect 0.43x4.7 smd: MP2(0,3.175) MP3(0,-3.175)
  silkscreen extent -3.9,-10.66 3.62,10.66, body extent -3.75,-10.64 3.75,10.67, height 3.25
Samtec_TSM-103-01-x-DV [mm] "Header, 2.54mm, 3x2, SMT"
  rect 3.68x1.27 smd: 1(-2.475,2.54) 2(2.475,2.54) 3(-2.475,0) 4(2.475,0) 5(-2.475,-2.54) 6(2.475,-2.54)
  silkscreen extent -1.75,-3.81 1.65,3.9, body extent -3.85,-3.81 3.85,3.81, height 9.65
SM_RADIAL_6.3BMM [mm] "Nichicon 6.3x7.7"
  rect 3.5x1.6 smd: 1(-2.7,0) 2(2.7,0)
  silkscreen extent -3.4,-3.4 3.4,3.4, body extent -3.4,-3.4 3.4,3.4, height 8
SMAF [mm] "SMD, 2-Leads, Body 3.8x2.5mm"
  rect 1.24x1.89 smd: 1(-2.04,0) 2(2.04,0)
  silkscreen extent -3.4,-1.3 2.8,1.3, body extent -2.35,-1.25 2.35,1.25, height 1
SML-E1_Yellow [mm] "SMD, 2-Leads, Body 1.6x0.8mm"
  rect 0.8x0.8 smd: 1(0.825,0) 2(-0.825,0)
  silkscreen extent -1.8,-0.8 1.3,0.8, body extent -0.85,-0.45 0.85,0.45, height 0.46
SML_Green_0805 [mm] "SMD, 2-Leads, Body 2x1.25mm"
  rrect8% 1.2x1.2 smd: 1(-1.05,0) 2(1.05,0)
  silkscreen extent -1.7,-1 2.3,1, body extent -1,-0.63 1,0.63, height 0.8
SOD-123 [mm] "On Semi recommended land pattern"
  rect 0.915x1.22 smd: 1(-1.637,0) 2(1.637,0)
  silkscreen extent -2.75,-1.17 2.03,1.17, body extent -1.93,-0.9 1.93,0.9, height 1.35
SOD-882 [mm] "Skyworks"
  rrect42% 0.475x0.75 smd mask+0.05: 1(-0.412,0) 2(0.412,0)
  silkscreen extent -1.1,-0.35 -0.88,0.35, body extent -0.5,-0.3 0.5,0.3, height 0.5
SOIC-8 [mm] "duplicate of SO-8.  SOIC, 8-Leads, Body 5.0x4.0mm (max), Pitch 1.27mm, IPC Medium Density"
  rrect17% 1.45x0.6 smd: 1(-2.725,1.905) 2(-2.725,0.635) 3(-2.725,-0.635) 4(-2.725,-1.905) 5(2.725,-1.905) 6(2.725,-0.635) 7(2.725,0.635) 8(2.725,1.905)
  silkscreen extent -3.5,-2.5 0.9,2.5, body extent -3,-2.45 3,2.45, height 1.63
SOT-23 [mm] "SOT23, 3-Leads, Body 2.9x1.3mm, Pitch 0.95mm, Lead Span 2.5mm, IPC Medium Density"
  rrect50% 1x0.6 smd: 1(-1.2,0.95) 2(-1.2,-0.95) 3(1.2,0)
  silkscreen extent -1.63,-1.5 0.7,1.5, body extent -1.16,-1.45 1.21,1.45, height 1
Sullins_GBC01SFBN-M30 [mil] "Header, 1x1, SMT"
  rrect8% 50x250 smd: 1(0,100)
  body extent -50,-50 50,150, height 490
SW_CJS_1201A [mm] "Copal- Electronics"
  rect 1x1.6 smd paste+0 mask+0.05: 1(-1.75,-1.15) 2(0,1.15) 3(1.75,-1.15)
  silkscreen extent -3,-1.6 -2.7,-0.8, body extent -3,-1.55 3,1.55, height 2.51
SW_KMR243GLFG [mm] "SMD, 5-Leads, Body 4.2x2.8mm"
  rrect11% 0.9x1 smd: 1(-2.05,0.8) 2(2.05,0.8) 3(-2.05,-0.8) 4(2.05,-0.8)
  rrect18% 1.7x0.55 smd: 5(0,1.425)
  silkscreen extent -3.1,0.7 -2.9,0.9, body extent -2.3,-1.4 2.3,1.4, height 1.92
TE_9-2304372-9 [mm] "Header(shrouded), 6 Power, 2 Signal, R/A, TH"
  rrect50% 1.5x1.5 hole 1: 1(-0.9,14)
  round 1.5 hole 1: 2(0.9,14) S1(-3.9,14) S2(-3.9,7) S3(-3.9,0) S4(3.9,14) S5(3.9,7) S6(3.9,0)
  round 2 hole 2.25 unplated: ALIGN1(0,0) ALIGN2(6.6,0)
  silkscreen extent -7.45,-5.15 10.3,15.95, body extent -7.45,-5.15 10.3,15.95, height 13.51
TFM201610ALMA [mm] "TDK"
  rrect17% 0.6x1.6 smd: 1(-0.9,0) 2(0.9,0)
  body extent -1.1,-0.9 1.1,0.9, height 1
TI_Stacked_Overlay_Small [mil]
  silkscreen extent -418,-98 418,98
TLMx1000_Yellow [mm] "SMD, 2-Leads, Body 1.6x0.8mm"
  rrect17% 0.6x0.8 smd: 1(-0.725,0) 2(0.725,0)
  silkscreen extent -0.97,-0.8 1.6,0.8, body extent -0.85,-0.45 0.85,0.45, height 0.65
TP_25MIL-SMT [mil]
  round 25 smd paste-25 mask-2.5: 1(0,0)
TSSOP-8 [mm] "TSSOP, 8-Leads, Body 3.1x4.5mm (max), Pitch 0.65mm, IPC Medium Density"
  rrect50% 1.7x0.35 smd: 1(-2.85,0.975) 2(-2.85,0.325) 3(-2.85,-0.325) 4(-2.85,-0.975) 5(2.85,-0.975) 6(2.85,-0.325) 7(2.85,0.325) 8(2.85,0.975)
  silkscreen extent -2.97,-1.55 1.6,1.82, body extent -3.2,-1.55 3.2,1.55, height 1.07
TSW-102-07-G-S [mm] "Samtec 100mil, 1x2, 230 mil above insulator"
  rrect50% 1.65x1.65 hole 1.016: 1(-1.27,0)
  round 1.65 hole 1.016: 2(1.27,0)
  silkscreen extent -3.17,-1.27 2.54,1.27, body extent -2.54,-1.27 2.54,1.27, height 8.38
VGROVE_1-6_45A [mil]
WEEE_Minimum [mil] "WEEElie bin"
  silkscreen extent -95,-172 99,104
XEL4030_310 [mm] "SMD, 2-Leads, Body 4x4mm, Pitch 2.37mm"
  rect 0.98x3.9 smd: 1(-1.185,0) 2(1.185,0)
  silkscreen extent -2.3,-2.3 2.3,2.3, body extent -2.15,-2.15 2.15,2.15, height 3.1
XTAL_ABM3 [mm] "Abracon recommended land pattern 12.28.10"
  rect 1.9x2.4 smd: 1(-2.05,0) 2(2.05,0)
  silkscreen extent -2.67,-1.78 2.67,1.78, body extent -2.6,-1.7 2.6,1.7, height 1.3

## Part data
C1 C10 C48 C53 C56 C59 C60 C65 C87 C90 C145 C159 C183 C186 C187 C190 C192: library part CMP-0007136-5, "CAP, CERM, 1 uF, 16 V, +/- 10%, X7R, AEC-Q200 Grade 1, 0603", Cap_Case=0603, Manufacturer=MuRata, Supplier Part Number 1=490-5241-6-ND, TempCo=X7R, Tolerance_%=10%, Value1=Unknown, Value2=16V, ValueDisplayed=1uF
C2 C80 C128: library part CMP-0006325-2, "CAP, CERM, 0.1 uF, 50 V, +/- 10%, X7R, AEC-Q200 Grade 1, 0402", Cap_Case=0402, Manufacturer=TDK, Supplier Part Number 1=445-6899-1-ND, TempCo=X7R, Tolerance_%=10%, Value1="0.039064 ohm", Value2=50V, ValueDisplayed=0.1uF
C3 C32 C40 C51 C123 C137 C146 C147 C149 C171: library part CMP-0007134-5, "CAP, CERM, 2.2 uF, 6.3 V, +/- 10%, X7R, AEC-Q200 Grade 1, 0603", Cap_Case=0603, Manufacturer=MuRata, Supplier Part Number 1=490-5316-1-ND, TempCo=X7R, Tolerance_%=10%, Value1=Unknown, Value2=6.3V, ValueDisplayed=2.2uF
C4 C152 C194 C198: library part CMP-0081061-1, "CAP, CERM, 10 µF, 10 V,+/- 5%, X7R, AEC-Q200 Grade 1, 0805", Cap_Case=0805, Manufacturer=Kemet, Supplier Part Number 1=399-15693-1-ND, TempCo=X7R, Tolerance_%=5%, Value2=10V, ValueDisplayed=10µF
C5 C21 C22 C92 C96 C107 C111 C113 C115 C117 C138 C139 C140 C141 C142 C163 C164 C165 C168 C170 C172 C174 C175 C176 C177 C199: library part CMP-0078265-1, "CAP, CERM, 0.22 µF, 16 V,+/- 10%, X7R, AEC-Q200 Grade 1, 0402", Cap_Case=0402, Manufacturer=MuRata, Supplier Part Number 1=490-10671-1-ND, TempCo=X7R, Tolerance_%=10%, Value2=16V, ValueDisplayed=0.22µF
C6 C8 C124 C144 C153: library part CMP-0091520-1, "Cap Ceramic Multilayer 4.7uF 6.3V DC 10% SMD Paper T/R", Manufacturer=Murata, Operating Temperature Range="-55°C to +125°C", TempCo=22%, Temperature Characteristic=X7S, Tolerance_%=10%, ValueDisplayed=4.7uF
C7 C15 C31 C37 C110 C112 C114 C116 C119 C120 C122 C196: library part CMP-0008017-2, "CAP, CERM, 10 uF, 10 V, +/- 10%, X7R, 0805", Cap_Case=0805, Manufacturer=MuRata, Supplier Part Number 1=490-10674-1-ND, TempCo=X7R, Tolerance_%=10%, Value1=Unknown, Value2=10V, ValueDisplayed=10uF
C9 C58 C181: library part CMP-0088247-2, "3 Terminals Low ESL Chip Multilayer Ceramic Capacitors for Automotive", Manufacturer=Murata, Tolerance_%=20%, ValueDisplayed=1uF
C11 C12 C16 C20 C36 C46 C54 C105 C131 C135 C136 C150 C200: library part CMP-0006351-2, "CAP, CERM, 0.1 uF, 16 V, +/- 10%, X7R, 0402", Cap_Case=0402, Manufacturer=MuRata, Supplier Part Number 1=490-4759-2-ND, TempCo=X7R, Tolerance_%=10%, Value1=Unknown, Value2=16V, ValueDisplayed=0.1uF
C13 C24: library part CMP-0006361-2, "CAP, CERM, 4700 pF, 50 V, +/- 10%, X7R, AEC-Q200 Grade 1, 0402", Cap_Case=0402, Manufacturer=MuRata, Supplier Part Number 1=490-4915-1-ND, TempCo=X7R, Tolerance_%=10%, Value1=Unknown, Value2=50V, ValueDisplayed=4700pF
C14 C17 C19 C57 C81 C148 C158 C160 C178 C184 C185 C188 C189 C191 C193: library part CMP-0006350-2, "CAP, CERM, 0.1 uF, 10 V, +/- 10%, X7R, AEC-Q200 Grade 1, 0402", Cap_Case=0402, Manufacturer=MuRata, Supplier Part Number 1=81-GCM155R71A104K5D, TempCo=X7R, Tolerance_%=10%, Value1=Unknown, Value2=10V, ValueDisplayed=0.1uF
C18 C42 C43 C47 C49 C64 C67 C69 C71 C73 C75 C76 C77 C78 C82 C86 C88 C89 C91 C97 C98 C133: library part CMP-0078241-1, "CAP, CERM, 0.1 µF, 10 V,+/- 10%, X7R, 0402", Cap_Case=0402, Manufacturer=Kemet, Supplier Part Number 1=399-3520-1-ND, TempCo=X7R, Tolerance_%=10%, Value2=10V, ValueDisplayed=0.1µF
C23 C25 C26 C29: library part CMP-0008811-3, "CAP, CERM, 22 uF, 10 V, +/- 10%, X7R, AEC-Q200 Grade 1, 1206", Cap_Case=1206, Manufacturer=MuRata, TempCo=X7R, Tolerance_%=10%, Value1=Unknown, Value2=10V, ValueDisplayed=22uF
C27 C28: library part CMP-0089508-1, "C0603 0.10 μF X7R 30ppm/°C 10.00% 16 V", Digikey Part Number=399-6855-2-ND, Manufacturer=KEMET, Mouser Part Number=80-C0603C104K4RAUTO, Operating Temperature Range="-55°C to +125°C", TempCo=30ppm/°C, Temperature Characteristic=X7R, Tolerance_%=0.1%, ValueDisplayed="0.10 μF"
C30 C33 C95 C121: library part CMP-0860920-1, "CAP, CERM, 27 pF, 50 V,+/- 5%, C0G/NP0, AEC-Q200 Grade 1, 0402", Cap_Case=0402, Manufacturer=MuRata, TempCo=C0G/NP0, Tolerance_%=5%, Value2=50V, ValueDisplayed=27pF
C34: library part CMP-0006354-2, "CAP, CERM, 1000 pF, 50 V, +/- 10%, X7R, AEC-Q200 Grade 1, 0402", Cap_Case=0402, Manufacturer=MuRata, Supplier Part Number 1=490-4761-1-ND, TempCo=X7R, Tolerance_%=10%, Value1=Unknown, Value2=50V, ValueDisplayed=1000pF
C35 C44 C52 C154 C182: library part CMP-0006324-2, "CAP, CERM, 0.01 uF, 50 V, +/- 10%, X7R, AEC-Q200 Grade 1, 0402", Cap_Case=0402, Manufacturer=TDK, Supplier Part Number 1=445-6893-1-ND, TempCo=X7R, Tolerance_%=10%, Value1="0.333065 ohm", Value2=50V, ValueDisplayed=0.01uF
C38: library part CMP-0007977-2, "CAP, CERM, 2.2 uF, 50 V, +/- 10%, X7R, AEC-Q200 Grade 1, 0805", Cap_Case=0805, Manufacturer=TDK, Supplier Part Number 1=445-174216-1-ND, TempCo=X7R, Tolerance_%=10%, Value1="0.003288 ohm", Value2=50V, ValueDisplayed=2.2uF
C39 C45: library part CMP-0007995-2, "CAP, CERM, 10 uF, 16 V, +/- 10%, X7R, 0805", Cap_Case=0805, Manufacturer="Samsung Electro-Mechanics", TempCo=X7R, Tolerance_%=10%, Value1=Unknown, Value2=16V, ValueDisplayed=10uF
C41 C61 C62: library part CMP-0006349-2, "CAP, CERM, 1 uF, 10 V, +/- 10%, X7S, AEC-Q200 Grade 1, 0402", Cap_Case=0402, Manufacturer=MuRata, Supplier Part Number 1=81-GCM155C71A105KE8D, TempCo=X7S, Tolerance_%=10%, Value1=Unknown, Value2=10V, ValueDisplayed=1uF
C50 C66 C109: library part CMP-0078218-1, "CAP, CERM, 0.01 µF, 16 V,+/- 10%, X7R, 0402", Cap_Case=0402, Manufacturer=Kemet, Supplier Part Number 1=399-1038-1-ND, TempCo=X7R, Tolerance_%=10%, Value2=16V, ValueDisplayed=0.01µF
C55: library part CMP-0006669-2, "CAP, CERM, 0.047 uF, 25 V, +/- 10%, X7R, 0402", Cap_Case=0402, Manufacturer=MuRata, Supplier Part Number 1=490-3254-1-ND, TempCo=X7R, Tolerance_%=10%, Value1=Unknown, Value2=25V, ValueDisplayed=0.047uF
C63 C70 C83 C84: library part CMP-0087060-3, "Cap Ceramic 8pF 50V C0G 0.5pF SMD 0402 125C Paper T/R", Manufacturer="Murata Electronics North America", TempCo=30ppm/°C
C68 C72 C79: library part CMP-0007058-4, "CAP, CERM, 4.7 uF, 10 V, +/- 10%, X7S, 0603", Cap_Case=0603, Manufacturer=TDK, Supplier Part Number 1=445-14258-1-ND, TempCo=X7S, Tolerance_%=10%, Value1=Unknown, Value2=10V, ValueDisplayed=4.7uF
C74 C85 C94: library part CMP-0006302-2, "CAP, CERM, 2.2 uF, 10 V, +/- 10%, X7S, 0402", Cap_Case=0402_065, Manufacturer=TDK, Supplier Part Number 1=445-9097-1-ND, TempCo=X7S, Tolerance_%=10%, Value1="0.005925 ohm", Value2=10V, ValueDisplayed=2.2uF
C93: library part CMP-0078217-1, "CAP, CERM, 15 pF, 50 V,+/- 1%, C0G/NP0, 0402", Cap_Case=0402, Manufacturer=AVX, Supplier Part Number 1=478-5126-1-ND, TempCo=C0G/NP0, Tolerance_%=1%, Value2=50V, ValueDisplayed=15pF
C99: library part CMP-0012608-3, "CAP, Polymer Hybrid, 68 uF, 35 V, +/- 20%, 35 ohm, 6.3x7.7 SMD", Manufacturer=Panasonic, Supplier Part Number 1=P15474CT-ND, Tolerance_%=20%, Value1="35 ohm", Value2=35V, ValueDisplayed=68uF
C100 C101: library part CMP-0008702-2, "CAP, CERM, 4.7 uF, 50 V, +/- 10%, X7R, 1206", Cap_Case=1206_180, Manufacturer=TDK, Supplier Part Number 1=445-8032-1-ND, TempCo=X7R, Tolerance_%=10%, Value1="0.003158 ohm", Value2=50V, ValueDisplayed=4.7uF
C102 C103: library part CMP-0088425-1, "1µF ±10% 6.3V Ceramic Capacitor X7R 0402 (1005 Metric)", Digikey Part Number=490-18216-1-ND, Manufacturer=Murata, Mouser Part Number=81-GRT155R70J105KE1D, Operating Temperature Range="-55°C to +125°C", TempCo=15%, Temperature Characteristic=X7R, Tolerance_%=10%, ValueDisplayed=1uF
C104 C126: library part CMP-0007104-4, "CAP, CERM, 0.1 uF, 50 V, +/- 10%, X8R, AEC-Q200 Grade 0, 0603", Cap_Case=0603, Manufacturer=TDK, Supplier Part Number 1=445-12606-1-ND, TempCo=X8R, Tolerance_%=10%, Value1=Unknown, Value2=50V, ValueDisplayed=0.1uF
C106 C108: library part CMP-0048219-1, "Ceramic Capacitor for Automotive 3.9pF ±0.1pF 50VDC C0G 0402 Paper T/R", Manufacturer=Murata, Operating Temperature Range="-55°C to +125°C", TempCo=30ppm/°C, Temperature Characteristic=C0G, ValueDisplayed=3.9pF
C118 C173: library part CMP-0090082-1, "Cap Ceramic 4.7uF 50V X7R 10% Pad SMD 0805 +125°C Automotive T/R", Manufacturer="TDK Corporation", Operating Temperature Range="-55°C to +125°C", TempCo=15%, Temperature Characteristic=X7R, Tolerance_%=0.1%, ValueDisplayed=4.7uF
C125 C127 C129 C130 C132 C134: library part CMP-0860846-1, "CAP, CERM, 22 µF, 6.3 V,+/- 20%, X7T, AEC-Q200 Grade 1, 0805", Alternate PartNumber=CGA4J1X7T0J226M125AC, Cap_Case=0805, Manufacturer=TDK, TempCo=X7T, Tolerance_%=20%, Value2=6.3V, ValueDisplayed=22µF
C143 C151 C169 C201 C202: library part CMP-0860846-1, "CAP, CERM, 22 µF, 6.3 V,+/- 20%, X7T, AEC-Q200 Grade 1, 0805", Cap_Case=0805, Manufacturer=TDK, TempCo=X7T, Tolerance_%=20%, Value2=6.3V, ValueDisplayed=22µF
C155 C166: library part CMP-0006467-2, "CAP, CERM, 47 pF, 50 V, +/- 1%, C0G/NP0, 0402", Cap_Case=0402, Manufacturer=MuRata, Supplier Part Number 1=490-6241-1-ND, TempCo=C0G/NP0, Tolerance_%=1%, Value1=Unknown, Value2=50V, ValueDisplayed=47pF
C156 C162: library part CMP-0006438-2, "CAP, CERM, 22 pF, 50 V, +/- 1%, C0G/NP0, 0402", Cap_Case=0402, Manufacturer=MuRata, Supplier Part Number 1=490-8589-1-ND, TempCo=C0G/NP0, Tolerance_%=1%, Value1=Unknown, Value2=50V, ValueDisplayed=22pF
C157 C161: library part CMP-0007969-2, "CAP, CERM, 0.1 uF, 100 V, +/- 10%, X7R, AEC-Q200 Grade 1, 0805", Cap_Case=0805, Manufacturer=TDK, Supplier Part Number 1=445-5827-1-ND, TempCo=X7R, Tolerance_%=10%, Value1="0.020726 ohm", Value2=100V, ValueDisplayed=0.1uF
C167: library part CMP-0008920-2, "CAP, CERM, 4700 pF, 1000 V, +/- 10%, X7R, 1206", Cap_Case=1206, Manufacturer=MuRata, Supplier Part Number 1=490-3498-1-ND, TempCo=X7R, Tolerance_%=10%, Value1=Unknown, Value2=1000V, ValueDisplayed=4700pF
C180: library part CMP-0006330-2, "CAP, CERM, 0.047 uF, 50 V, +/- 10%, X7R, AEC-Q200 Grade 1, 0402", Cap_Case=0402, Manufacturer=TDK, Supplier Part Number 1=445-6897-1-ND, TempCo=X7R, Tolerance_%=10%, Value1="0.06407 ohm", Value2=50V, ValueDisplayed=0.047uF
C195: library part CMP-0007094-5, "CAP, CERM, 0.22 uF, 50 V, +/- 10%, X7R, AEC-Q200 Grade 1, 0603", Cap_Case=0603, Manufacturer=TDK, Supplier Part Number 1=445-6926-1-ND, TempCo=X7R, Tolerance_%=10%, Value1="0.021699 ohm", Value2=50V, ValueDisplayed=0.22uF
C197: library part CMP-0860898-1, "CAP, CERM, 10 µF, 50 V,+/- 10%, X7R, AEC-Q200 Grade 1, 1206", Cap_Case=1206, Manufacturer=TDK, TempCo=X7R, Tolerance_%=10%, Value2=50V, ValueDisplayed=10µF
"CAUTION HOT SURFACE1": library part CMP-0074837-1, "IEC 61010-1 Hot Surface Warning"
D1: library part CMP-0078196-2, "LED, Yellow, SMD", Color=yellow, Manufacturer=Vishay-Semiconductor, Power_TotalModule=40mW, Value1=.04W, Value2=1.8V
D2 D4 D5: library part CMP-0078187-3, "Diode, Schottky,  V, 0.01 A, SOD-882", Manufacturer="Skyworks Solutions", Value1=0.01A, Value2=0.34V
D3: library part CMP-0005735-3, "Diode, TVS, Bi, 28 V, 45.4 Vc, AEC-Q101, SOD-123", Manufacturer="Comchip Technology", Value1=200W
D6 D12 D16: library part CMP-0003042-3, "LED, Green, SMD", Color=Green, Manufacturer=Lumex, Power_TotalModule=50mW, Value1=0.05W, Value2=2V
D7 D8 DS2: library part CMP-0002902-2, "LED, Red, SMD", Color=Red, Manufacturer=OSRAM, Value1=W, Value2=1.8V
D9 D13: library part CMP-0002977-3, "LED, Yellow, SMD", Color=yellow, Manufacturer=Rohm, Power_TotalModule=54mW, Value1=0.054W, Value2=2.2V
D10: library part CMP-0002839-2, "LED, Yellow, SMD", Color=yellow, Manufacturer=Rohm, Value1=W, Value2=2.1V
D11: library part CMP-0077017-3, "Diode, Schottky, 30 V, 5 A, SOD-128", Manufacturer="Fairchild Semiconductor", Value1=5A, Value2=0.54V
D14: library part CMP-0002841-1, "LED, Orange, SMD", Color=orange, Manufacturer=Rohm, Supplier Part Number 1=511-1590-1-ND, Value1=W, Value2=2.1V
D15 D17 D18 D19: library part CMP-0073591-4, "Automotive 1-Channel Ultra-Low-Capacitance IEC ESD Protection Diode, DPY0002A (X1SON-2)", Alternate Manufacturer="Texas Instruments", Alternate PartNumber=TPD1E05U06QDPYTQ1, Operating Temperature Range="-40 to 125 C", Rating=Automotive
"ESD Susceptible1": library part CMP-0074840-1, "ESD Susceptible Symbol"
FB1: library part CMP-0003348-2, "Ferrite Bead, 1000 ohm @ 100 MHz, 0.6 A, 0603", Manufacturer=MuRata, Supplier Part Number 1=490-5215-1-ND, Value1="0.35 ohm", Value2=0.6A, ValueDisplayed="1000 ohm"
FB2 R48: library part CMP-0089848-1, "600 Ohms @ 100MHz 1 Power Line Ferrite Bead 0603 (1608 Metric) 1.3A 150mOhm", Digikey Part Number=490-13259-1-ND, Impedance At Frequency="600Ω @ 100MHz", Manufacturer=Murata, Mouser Part Number=81-BLM18KG601SH1D, Operating Temperature Range="-55°C to +125°C", Test Frequency=100MHz, Tolerance_%=25%
FID1 FID2 FID3 FID4 FID5 FID6 FID7 FID8 FID9 FID10 FID11 FID12 FID13 FID14 FID15 FID16: library part CMP-0077181-1, "Fiducial mark.  There is nothing to buy or mount.", Manufacturer=N/A
J1 J5: library part CMP-0091846-1, "U.FL (UMCC) Connector Jack, Male Pin 50Ohm Surface Mount Solder", Dielectric Material="Liquid Crystal Polymer", Digikey Part Number=A118077CT-ND, Frequency_Fixed=0-6GHz, Manufacturer="TE Connectivity", Mouser Part Number=571-1909763-1, Operating Temperature Range="-40°C to +90°C"
J2 J3: library part CMP-0091742-1, "3 Position Wire to Board Terminal Block Vertical with Board 0.138\" (3.50mm) Through Hole", Current_A=10A, Digikey Part Number=ED2624-ND, Manufacturer="On Shore Technology", Operating Temperature Range="-40°C to +105°C", Voltage_V=150V
J4: library part CMP-0078655-1, "1 Port Header Assembly, TH", Color=Blue, Manufacturer="TE Connectivity"
J7: library part CMP-0075524-1, "Receptacle, 0.5 mm, 30x2, Gold, TH", Color=Black, Manufacturer=Samtec, Supplier Part Number 1=SAM8180-ND
J8 J10: library part CMP-0055293-1, "Connector, Receptacle, Micro-USB Type B, R/A, Bottom Mount SMT", Manufacturer=Molex, Supplier Part Number 1=WM1399CT-ND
